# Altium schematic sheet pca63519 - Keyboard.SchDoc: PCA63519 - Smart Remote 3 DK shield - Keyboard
size A4; DocumentNumber: 4; Revision: 1.2.1; SheetNumber: 4; SheetTotal: 6; DrawnBy: GETR; ProjectNumber: 4414; DocumentSize: A4; PCBRevision: 0049GETR; PCAName: PCA63519; PCBNumber: 400129
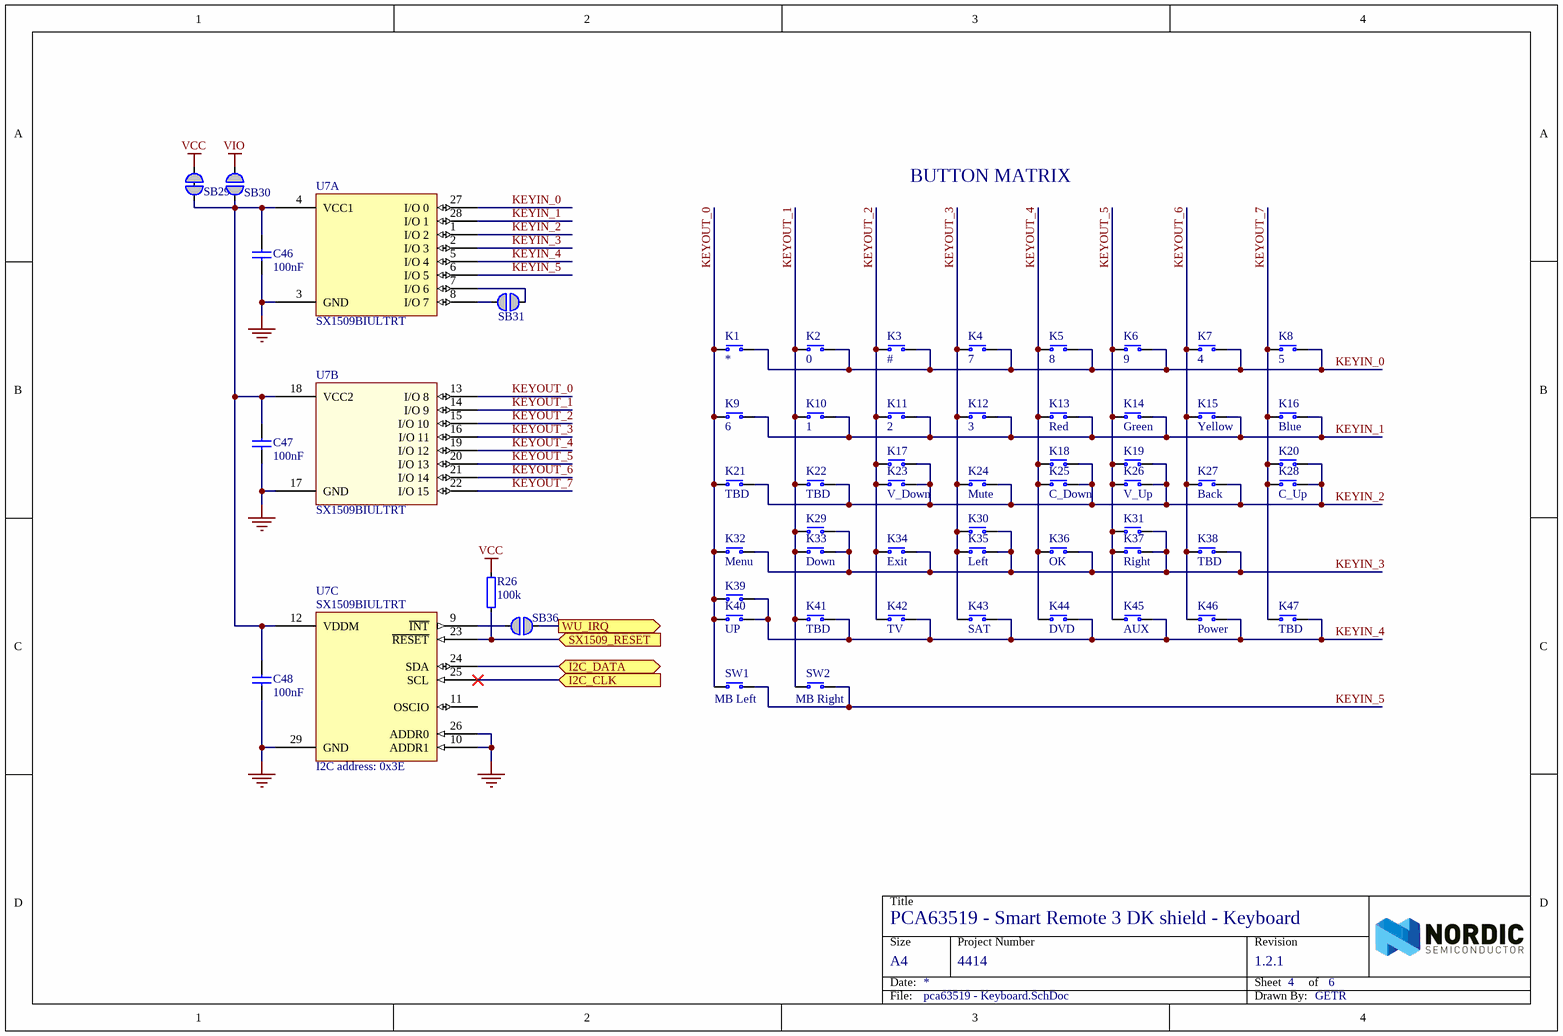
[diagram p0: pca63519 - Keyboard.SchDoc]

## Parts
C46  100nF  [CAPC1005X04L]
C47  100nF  [CAPC1005X04L]
C48  100nF  [CAPC1005X04L]
K1  *  [PCB Switch]  (no BOM)
K2  0  [PCB Switch]  (no BOM)
K3  #  [PCB Switch]  (no BOM)
K4  7  [PCB Switch]  (no BOM)
K5  8  [PCB Switch]  (no BOM)
K6  9  [PCB Switch]  (no BOM)
K7  4  [PCB Switch]  (no BOM)
K8  5  [PCB Switch]  (no BOM)
K9  6  [PCB Switch]  (no BOM)
K10  1  [PCB Switch]  (no BOM)
K11  2  [PCB Switch]  (no BOM)
K12  3  [PCB Switch]  (no BOM)
K13  Red  [PCB Switch]  (no BOM)
K14  Green  [PCB Switch]  (no BOM)
K15  Yellow  [PCB Switch]  (no BOM)
K16  Blue  [PCB Switch]  (no BOM)
K17  PCB SW  [PCB Switch]  (value not drawn)  (no BOM)
K18  PCB SW  [PCB Switch]  (value not drawn)  (no BOM)
K19  PCB SW  [PCB Switch]  (value not drawn)  (no BOM)
K20  PCB SW  [PCB Switch]  (value not drawn)  (no BOM)
K21  TBD  [PCB Switch]  (no BOM)
K22  TBD  [PCB Switch]  (no BOM)
K23  V_Down  [PCB Switch]  (no BOM)
K24  Mute  [PCB Switch]  (no BOM)
K25  C_Down  [PCB Switch]  (no BOM)
K26  V_Up  [PCB Switch]  (no BOM)
K27  Back  [PCB Switch]  (no BOM)
K28  C_Up  [PCB Switch]  (no BOM)
K29  PCB SW  [PCB Switch]  (value not drawn)  (no BOM)
K30  PCB SW  [PCB Switch]  (value not drawn)  (no BOM)
K31  PCB SW  [PCB Switch]  (value not drawn)  (no BOM)
K32  Menu  [PCB Switch]  (no BOM)
K33  Down  [PCB Switch]  (no BOM)
K34  Exit  [PCB Switch]  (no BOM)
K35  Left  [PCB Switch]  (no BOM)
K36  OK  [PCB Switch]  (no BOM)
K37  Right  [PCB Switch]  (no BOM)
K38  TBD  [PCB Switch]  (no BOM)
K39  PCB SW  [PCB Switch]  (value not drawn)  (no BOM)
K40  UP  [PCB Switch]  (no BOM)
K41  TBD  [PCB Switch]  (no BOM)
K42  TV  [PCB Switch]  (no BOM)
K43  SAT  [PCB Switch]  (no BOM)
K44  DVD  [PCB Switch]  (no BOM)
K45  AUX  [PCB Switch]  (no BOM)
K46  Power  [PCB Switch]  (no BOM)
K47  TBD  [PCB Switch]  (no BOM)
R26  100k  [RESC1005X04L]
SB29  Solderbridge  [Solderbridge_SHORTED_0.4]  (value not drawn)  (net tie, no BOM)
SB30  Solderbridge  [Solderbridge_0.4]  (value not drawn)  (no BOM)
SB31  Solderbridge  [Solderbridge_0.4]  (value not drawn)  (no BOM)
SB36  Solderbridge  [Solderbridge_0.4]  (value not drawn)  (no BOM)
SW1  MB Left  [ALPS_SKHUxxx010_WO_GND]
SW2  MB Right  [ALPS_SKHUxxx010_WO_GND]
U7  SX1509BIULTRT  [QFN40P400X400X60_HS-29N]  (parts A,B,C of 3)

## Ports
I2C_CLK (in), I2C_DATA (bidir), SX1509_RESET (in), WU_IRQ (out)

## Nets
GND: C46.1 C47.1 C48.1 U7.3(GND) U7.10(ADDR1) U7.17(GND) U7.26(ADDR0) U7.29(GND)
VCC: R26.2 SB29.1
VIO: SB30.1
I2C_CLK: U7.25(SCL) ; port I2C_CLK
I2C_DATA: U7.24(SDA) ; port I2C_DATA
KEYIN_0: K1.1(N.O) K2.1(N.O) K3.1(N.O) K4.1(N.O) K5.1(N.O) K6.1(N.O) K7.1(N.O) K8.1(N.O) U7.27(I/O_0)
KEYIN_1: K9.1(N.O) K10.1(N.O) K11.1(N.O) K12.1(N.O) K13.1(N.O) K14.1(N.O) K15.1(N.O) K16.1(N.O) U7.28(I/O_1)
KEYIN_2: K17.1(N.O) K18.1(N.O) K19.1(N.O) K20.1(N.O) K21.1(N.O) K22.1(N.O) K23.1(N.O) K24.1(N.O) K25.1(N.O) K26.1(N.O) K27.1(N.O) K28.1(N.O) U7.1(I/O_2)
KEYIN_3: K29.1(N.O) K30.1(N.O) K31.1(N.O) K32.1(N.O) K33.1(N.O) K34.1(N.O) K35.1(N.O) K36.1(N.O) K37.1(N.O) K38.1(N.O) U7.2(I/O_3)
KEYIN_4: K39.1(N.O) K40.1(N.O) K41.1(N.O) K42.1(N.O) K43.1(N.O) K44.1(N.O) K45.1(N.O) K46.1(N.O) K47.1(N.O) U7.5(I/O_4)
KEYIN_5: SW1.1(N.O) SW2.1(N.O) U7.6(I/O_5)
KEYOUT_0: K1.2(COM) K9.2(COM) K21.2(COM) K32.2(COM) K39.2(COM) K40.2(COM) SW1.2(COM) U7.13(I/O_8)
KEYOUT_1: K2.2(COM) K10.2(COM) K22.2(COM) K29.2(COM) K33.2(COM) K41.2(COM) SW2.2(COM) U7.14(I/O_9)
KEYOUT_2: K3.2(COM) K11.2(COM) K17.2(COM) K23.2(COM) K34.2(COM) K42.2(COM) U7.15(I/O_10)
KEYOUT_3: K4.2(COM) K12.2(COM) K24.2(COM) K30.2(COM) K35.2(COM) K43.2(COM) U7.16(I/O_11)
KEYOUT_4: K5.2(COM) K13.2(COM) K18.2(COM) K25.2(COM) K36.2(COM) K44.2(COM) U7.19(I/O_12)
KEYOUT_5: K6.2(COM) K14.2(COM) K19.2(COM) K26.2(COM) K31.2(COM) K37.2(COM) K45.2(COM) U7.20(I/O_13)
KEYOUT_6: K7.2(COM) K15.2(COM) K27.2(COM) K38.2(COM) K46.2(COM) U7.21(I/O_14)
KEYOUT_7: K8.2(COM) K16.2(COM) K20.2(COM) K28.2(COM) K47.2(COM) U7.22(I/O_15)
SX1509_RESET: R26.1 U7.23(~{RESET}) ; port SX1509_RESET
WU_IRQ: SB36.1 ; port WU_IRQ
NetC46_2: C46.2 C47.2 C48.2 SB29.2 SB30.2 U7.4(VCC1) U7.12(VDDM) U7.18(VCC2)
NetSB31_1: SB31.1 U7.8(I/O_7)
NetSB31_2: SB31.2 U7.7(I/O_6)
NetSB36_2: SB36.2 U7.9(~{INT})

Not connected (* = marked no-connect by the designer): U7 11(OSCIO)

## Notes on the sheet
- BUTTON MATRIX
- (near U7) I2C address: 0x3E

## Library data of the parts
C46-C48 = C0402-100n: Capacitor, X7R, ±10%; Note: 16V; Artikkelnr Noca: 20039200; Artikkelnr Simpro: N.A.
K1-K16 K21-K28 K32-K38 K40-K47 = KEY_SWITCH_SR3: Keyboard matrix switch; Value: PCB SW; Artikkelnr Noca: N.A.
K17-K20 K29-K31 K39 = KEY_SWITCH_SR3: Keyboard matrix switch; Artikkelnr Noca: N.A.
R26 = R0402-100k: Resistor, ±1%, 0.063W; Note: Chip Res 1%; Artikkelnr Noca: 27049121; Artikkelnr Simpro: N.A.; Value Ohm: 100000
SB29 = Solderbridge Shorted 0.4mm: Shorted Solderbridge; Artikkelnr Noca: N.A.
SB30 SB31 SB36 = Solderbridge 0.4mm: Artikkelnr Noca: N.A.
SW1 SW2 = ALPS_SKHUALE010: ALPS - SKHUALE010 - Tactile Switch, SPNO, SMD, 6.5x6.2x2.5mm; 2nd source part number: 688-SKHUALE010; Value: PB SW; Artikkelnr Noca: 50019001; Artikkelnr Simpro: N.A.
U7 = SX1509BIULTRT: IC GPIO EXPANDER I2C 16CH 28QFN; Manufacturer: Semtech Corporation; Artikkelnr Noca: N.A.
